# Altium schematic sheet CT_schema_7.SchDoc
size 310 x 315 mm
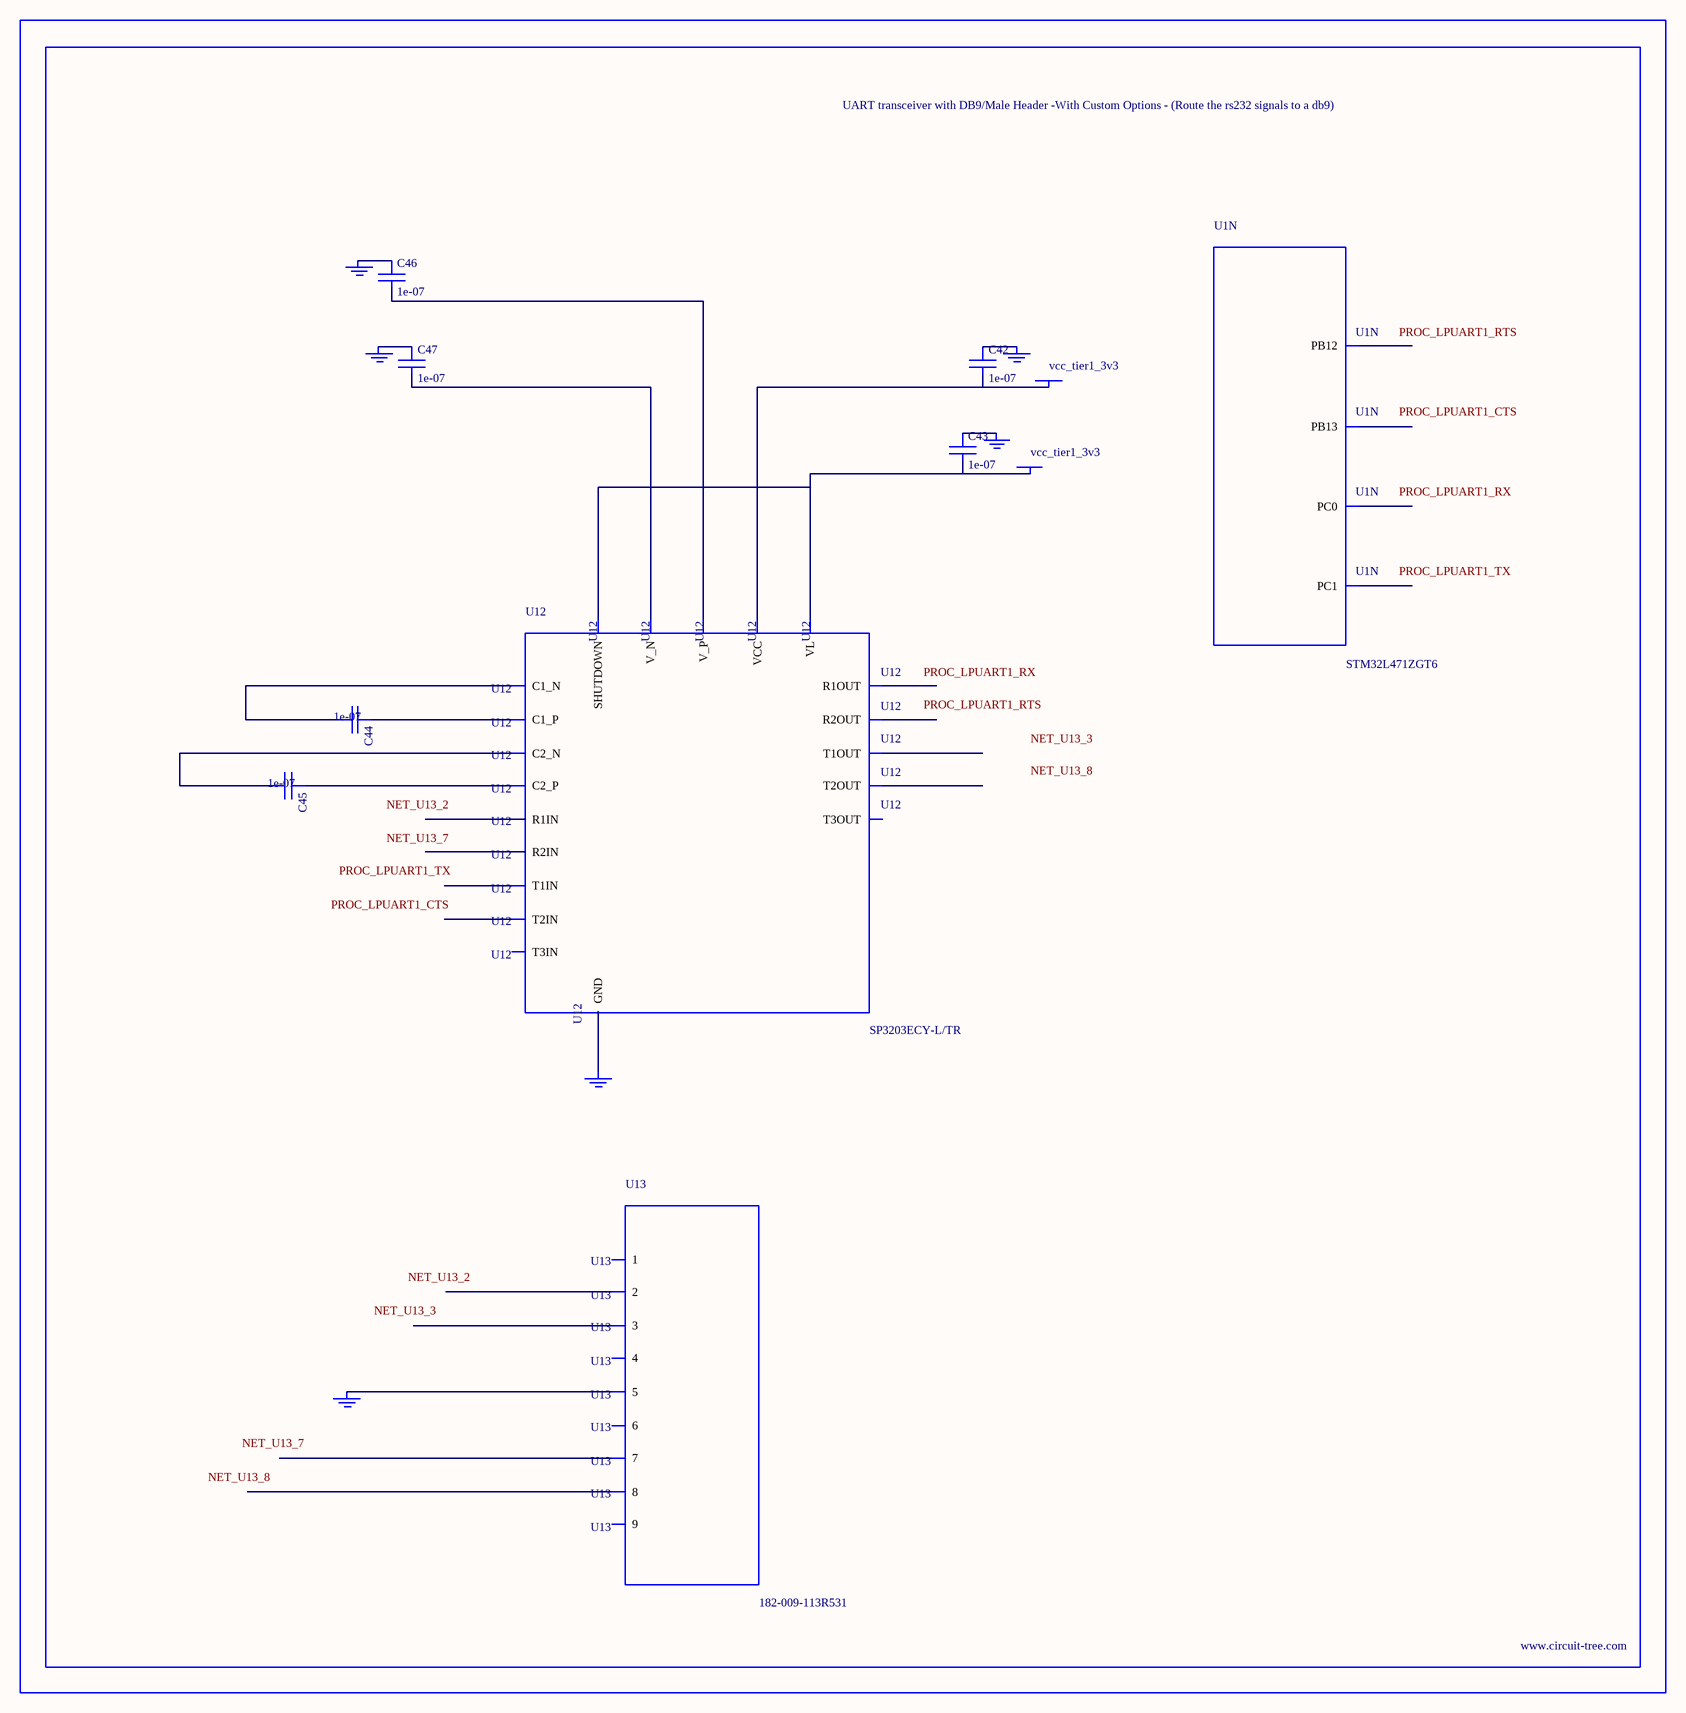
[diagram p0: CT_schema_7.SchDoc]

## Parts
BORDER6  (no value)
C42  1e-07  [C0402]
C43  1e-07  [C0402]
C44  1e-07  [C0402]
C45  1e-07  [C0402]
C46  1e-07  [C0402]
C47  1e-07  [C0402]
GND_INSTANCE_6_0  (no value)
GND_INSTANCE_6_1  (no value)
GND_INSTANCE_6_2  (no value)
GND_INSTANCE_6_3  (no value)
GND_INSTANCE_6_4  (no value)
GND_INSTANCE_6_5  (no value)
POWER_INSTANCE_6_0  vcc_tier1_3v3
POWER_INSTANCE_6_1  vcc_tier1_3v3
U1  STM32L471ZGT6  [LQFP144]  (part N of 14)
U12  SP3203ECY-L/TR  [TSSOP20-I]
U13  182-009-113R531  [182-009-MALE]

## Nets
NetC42_1: C42.1 GND_INSTANCE_6_3.0(GND)
NetC42_2: C42.2 POWER_INSTANCE_6_1.0(PWR) U12.19(VCC)
NetC43_1: C43.1 GND_INSTANCE_6_2.0(GND)
NetC43_2: C43.2 POWER_INSTANCE_6_0.0(PWR) U12.12(VL) U12.20(SHUTDOWN)
NetC44_1: C44.1 U12.1(C1_P)
NetC44_2: C44.2 U12.3(C1_N)
NetC45_1: C45.1 U12.4(C2_P)
NetC45_2: C45.2 U12.5(C2_N)
NetC46_1: C46.1 GND_INSTANCE_6_0.0(GND)
NetC46_2: C46.2 U12.2(V_P)
NetC47_1: C47.1 GND_INSTANCE_6_1.0(GND)
NetC47_2: C47.2 U12.6(V_N)
NetGND_INSTANCE_6_4_0: GND_INSTANCE_6_4.0(GND) U12.18(GND)
NetGND_INSTANCE_6_5_0: GND_INSTANCE_6_5.0(GND) U13.5

Not connected (* = marked no-connect by the designer): U1 26(PC0) 27(PC1) 73(PB12) 74(PB13); U12 7(T1IN) 8(T2IN) 9(T3IN) 10(R2OUT) 11(R1OUT) 13(R2IN) 14(R1IN) 15(T3OUT) 16(T2OUT) 17(T1OUT); U13 1 2 3 4 6 7 8 9

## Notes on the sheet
- Labels drawn without touching a wire or pin: NET_U13_2, NET_U13_3, NET_U13_7, NET_U13_8, PROC_LPUART1_CTS, PROC_LPUART1_RTS, PROC_LPUART1_RX, PROC_LPUART1_TX

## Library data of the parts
BORDER6 = BORDER_PAGE6
C42-C47 = C0402C104K3RACTU
GND_INSTANCE_6_0-GND_INSTANCE_6_5 = GND
POWER_INSTANCE_6_0 POWER_INSTANCE_6_1 = PWR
